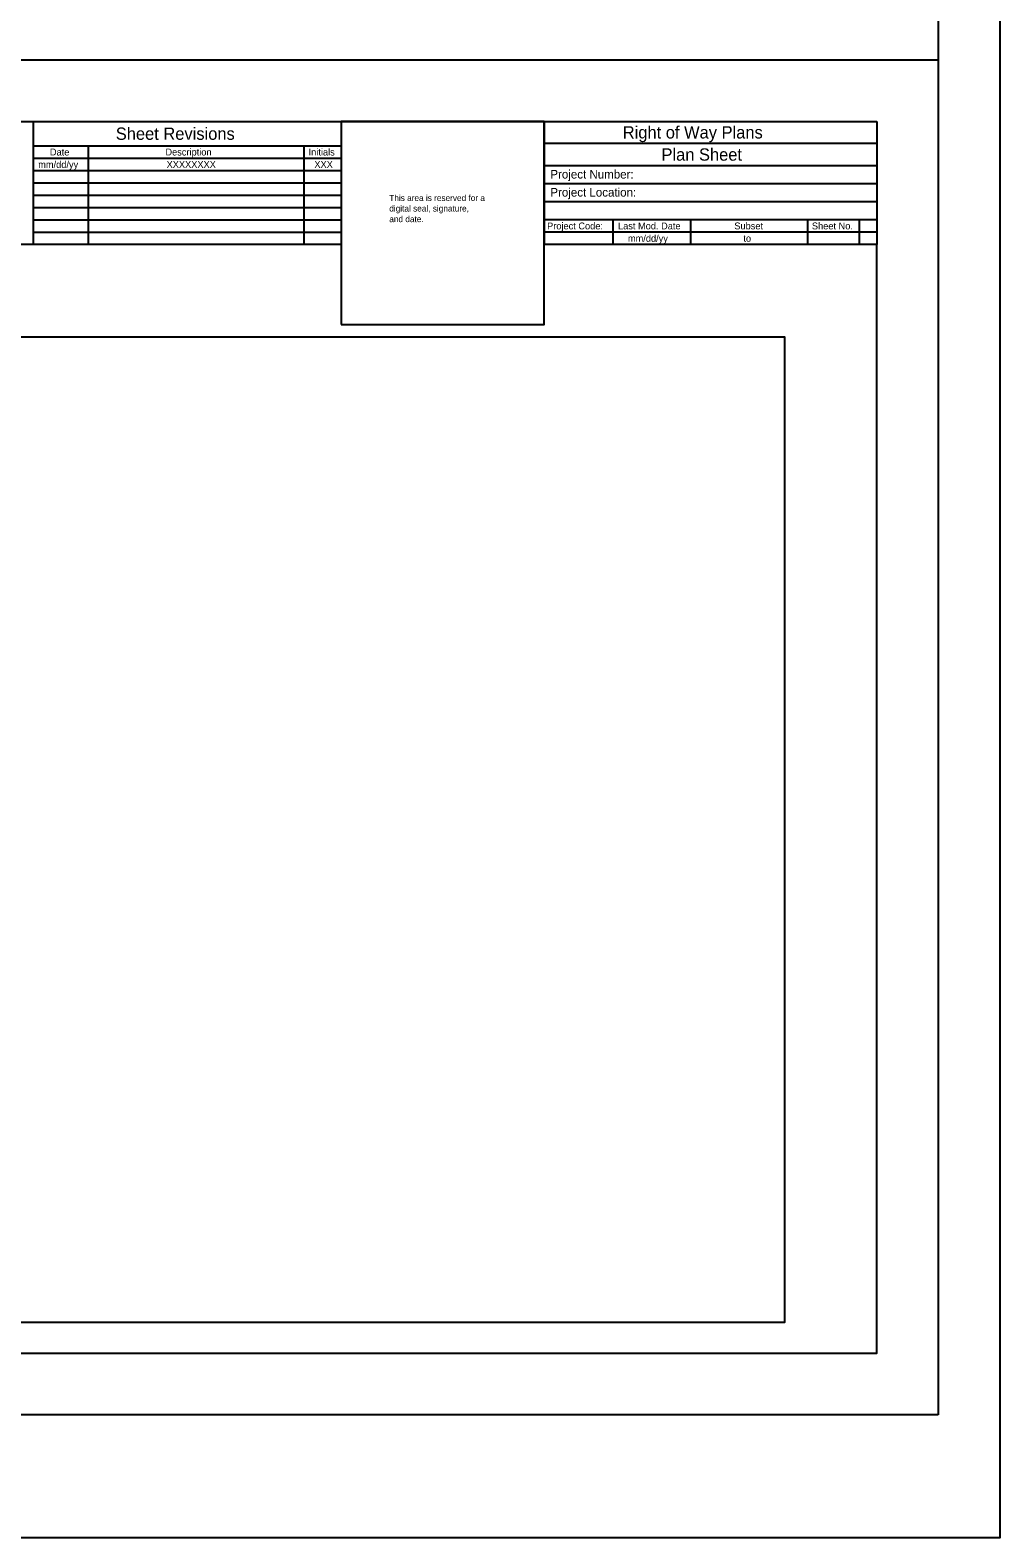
# Model space of a CAD drawing. Extents: x 0 to 3, y 0 to 2.
# Drawn here: x 2.344 to 3, y 0 to 1.02 of the extents above; entities that cross this region are included whole.
import ezdxf

# ---------------------------------------------------------------- set-up
doc = ezdxf.new("R2010")
doc.units = 0
for name, color, linetype in [('DRAFT_Information-No Plot', 7, 'Continuous'), ('SHEET_Lines', 7, 'Continuous'), ('SHEET_North Arrow', 7, 'Continuous'), ('SHEET_Plot Boundary', 7, 'Continuous'), ('SHEET_Text-Border Info', 7, 'Continuous')]:
    doc.layers.add(name, color=color, linetype=linetype)

msp = doc.modelspace()

# ---------------------------------------------------------------- linework, layer by layer
at = {"layer": 'DRAFT_Information-No Plot'}
msp.add_lwpolyline([(1.6875, 0.8125), (2.8542, 0.8125), (2.8542, 0.1458), (1.6875, 0.1458)], close=True, dxfattribs=at)
at = {"layer": 'SHEET_Lines'}
for p, q in [((0.125, 1), (2.9583, 1)), ((1.625, 0.9583), (2.9167, 0.9583)), ((2.3458, 0.9583), (2.3458, 0.875)), ((2.5542, 0.9583), (2.5542, 0.875)), ((2.6917, 0.9583), (2.6917, 0.875)), ((2.9167, 0.9583), (2.9167, 0.875)), ((2.3458, 0.9417), (2.5542, 0.9417)), ((2.3833, 0.875), (2.3833, 0.9417)), ((2.5292, 0.875), (2.5292, 0.9417)), ((2.9167, 0.9433), (2.6917, 0.9433)), ((2.3458, 0.9333), (2.5542, 0.9333)), ((2.9167, 0.9283), (2.6917, 0.9283)), ((2.3458, 0.925), (2.5542, 0.925)), ((2.3458, 0.9167), (2.5542, 0.9167)), ((2.3458, 0.9083), (2.5542, 0.9083)), ((2.9167, 0.9161), (2.6917, 0.9161)), ((2.3458, 0.9), (2.5542, 0.9)), ((2.9167, 0.9039), (2.6917, 0.9039)), ((2.3458, 0.8917), (2.5542, 0.8917)), ((2.9167, 0.8917), (2.6917, 0.8917)), ((2.7383, 0.875), (2.7383, 0.8917)), ((2.7908, 0.875), (2.7908, 0.8917)), ((2.87, 0.875), (2.87, 0.8917)), ((2.905, 0.875), (2.905, 0.8917)), ((2.3458, 0.8833), (2.5542, 0.8833)), ((2.9167, 0.8833), (2.6917, 0.8833))]:
    msp.add_line(p, q, dxfattribs=at)
for points in [[(2.9583, 0.0833), (0.125, 0.0833), (0.125, 1.9167), (2.9583, 1.9167)], [(2.5542, 0.8208), (2.6917, 0.8208), (2.6917, 0.9583), (2.5542, 0.9583)]]:
    msp.add_lwpolyline(points, close=True, dxfattribs=at)
msp.add_lwpolyline([(2.5542, 0.875), (1.625, 0.875), (1.625, 0.125), (2.9167, 0.125), (2.9167, 0.875), (2.6917, 0.875)], dxfattribs=at)
at = {"layer": 'SHEET_Plot Boundary'}
msp.add_lwpolyline([(0, 2), (3, 2), (3, 0), (0, 0)], close=True, dxfattribs=at)

# ---------------------------------------------------------------- texts
at = {"layer": 'DRAFT_Information-No Plot'}
for s, height, p in [('This area is reserved for a', 0.004167, (2.5868, 0.9044)), ('digital seal, signature,', 0.004167, (2.5868, 0.8973)), ('and date.', 0.00417, (2.5868, 0.8901))]:
    msp.add_text(s, height=height, dxfattribs=at).set_placement(p)
at = {"layer": 'SHEET_North Arrow'}
for s, height, p in [('Sheet Revisions', 0.008333, (2.4017, 0.9458)), ('Right of Way Plans', 0.008333, (2.7448, 0.9467)), ('Plan Sheet', 0.00833, (2.771, 0.9317))]:
    msp.add_text(s, height=height, dxfattribs=at).set_placement(p)
at = {"layer": 'SHEET_Text-Border Info'}
for s, height, p in [('Date', 0.00467, (2.3571, 0.9352)), ('Description', 0.004667, (2.4353, 0.9352)), ('Initials', 0.00467, (2.5322, 0.9352)), ('mm/dd/yy', 0.00467, (2.3492, 0.9268)), ('XXXXXXXX', 0.00467, (2.4361, 0.9268)), ('XXX', 0.00467, (2.5361, 0.9268)), ('Project Number:', 0.005833, (2.6958, 0.9196)), ('Project Location:', 0.005833, (2.6958, 0.9074)), ('Project Code:', 0.004667, (2.6936, 0.8852)), ('Last Mod. Date', 0.004667, (2.7416, 0.8852)), ('Subset', 0.00467, (2.8203, 0.8852)), ('Sheet No.', 0.00467, (2.8728, 0.8852)), ('mm/dd/yy', 0.00467, (2.7483, 0.8768)), (' to ', 0.00467, (2.8247, 0.8768))]:
    msp.add_text(s, height=height, dxfattribs=at).set_placement(p)

doc.saveas('drawing.dxf')
